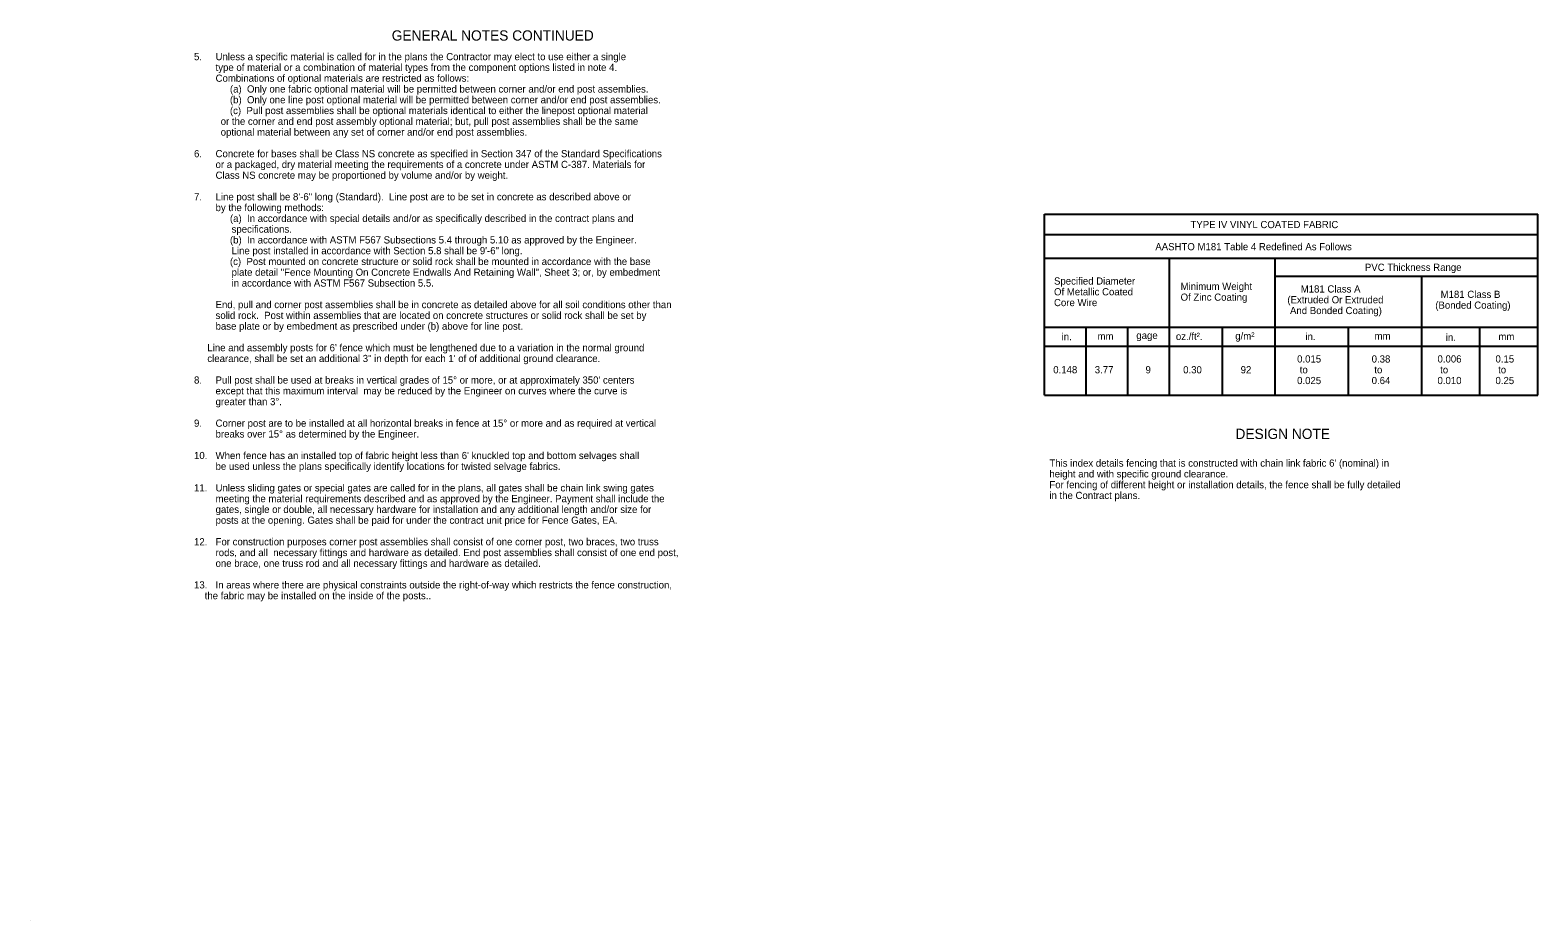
# Model space of a CAD drawing. Extents: x 10000 to 10735, y 10000 to 10434.
import ezdxf

# ---------------------------------------------------------------- set-up
doc = ezdxf.new("R2010")
doc.units = 0
for name, color, linetype in [('AdhocPoint_dp', 7, 'Continuous'), ('Default', 7, 'Continuous'), ('IndexDetail_1', 7, 'Continuous'), ('IndexDetail_2', 7, 'Continuous'), ('TextStructures', 7, 'Continuous')]:
    doc.layers.add(name, color=color, linetype=linetype)

msp = doc.modelspace()

# ---------------------------------------------------------------- linework, layer by layer
at = {"layer": 'AdhocPoint_dp'}
msp.add_line((10000, 10000), (10000, 10000), dxfattribs=at)
at = {"layer": 'Default'}
msp.add_line((10000, 10000), (10000, 10000), dxfattribs=at)
at = {"layer": 'IndexDetail_1'}
for p, q in [((10494.32, 10334.22), (10734.67, 10334.22)), ((10494.32, 10322.7), (10734.67, 10322.7)), ((10555.24, 10255.98), (10555.24, 10322.7)), ((10606.71, 10255.98), (10606.71, 10322.7)), ((10606.71, 10313.86), (10734.67, 10313.86)), ((10678.17, 10255.98), (10678.17, 10313.86)), ((10494.32, 10289.08), (10734.67, 10289.08)), ((10514.63, 10255.98), (10514.63, 10289.08)), ((10534.93, 10255.98), (10534.93, 10289.08)), ((10580.97, 10255.98), (10580.97, 10289.08)), ((10642.44, 10255.98), (10642.44, 10289.08)), ((10706.42, 10255.98), (10706.42, 10289.08)), ((10494.32, 10279.83), (10734.67, 10279.83))]:
    msp.add_line(p, q, dxfattribs=at)
at = {"layer": 'IndexDetail_2'}
for p, q in [((10494.32, 10255.98), (10494.32, 10344.12)), ((10494.32, 10344.12), (10734.67, 10344.12)), ((10734.67, 10255.98), (10734.67, 10344.12)), ((10494.32, 10255.98), (10734.67, 10255.98))]:
    msp.add_line(p, q, dxfattribs=at)

# ---------------------------------------------------------------- texts
at = {"layer": 'TextStructures'}
for s, height, p in [('GENERAL NOTES CONTINUED', 5, (10176.19, 10428.66)), ('5.', 3.5, (10079.85, 10419.11)), ('Unless a specific material is called for in the plans the Contractor may elect to use either a single', 3.5, (10090.35, 10419.11)), ('type of material or a combination of material types from the component options listed in note 4. ', 3.5, (10090.35, 10413.86)), ('Combinations of optional materials are restricted as follows:', 3.5, (10090.35, 10408.61)), ('(a)  Only one fabric optional material will be permitted between corner and/or end post assemblies.', 3.5, (10097.35, 10403.36)), ('(b)  Only one line post optional material will be permitted between corner and/or end post assemblies.', 3.5, (10097.35, 10398.11)), ('(c)  Pull post assemblies shall be optional materials identical to either the linepost optional material', 3.5, (10097.35, 10392.86)), ('          or the corner and end post assembly optional material; but, pull post assemblies shall be the same', 3.5, (10079.85, 10387.61)), ('          optional material between any set of corner and/or end post assemblies.', 3.5, (10079.85, 10382.36)), ('6.', 3.5, (10079.85, 10371.86)), ('Concrete for bases shall be Class NS concrete as specified in Section 347 of the Standard Specifications', 3.5, (10090.35, 10371.86)), ('or a packaged, dry material meeting the requirements of a concrete under ASTM C-387. Materials for', 3.5, (10090.35, 10366.61)), ('Class NS concrete may be proportioned by volume and/or by weight.', 3.5, (10090.35, 10361.36)), ('7.', 3.5, (10079.85, 10350.86)), ('Line post shall be 8\'-6" long (Standard).  Line post are to be set in concrete as described above or ', 3.5, (10090.35, 10350.86)), ('by the following methods:', 3.5, (10090.35, 10345.61)), ('(a)  In accordance with special details and/or as specifically described in the contract plans and', 3.5, (10097.35, 10340.36)), ('      specifications.', 3.5, (10090.35, 10335.11)), ('TYPE IV VINYL COATED FABRIC', 3.5, (10565.41, 10337.33)), ('(b)  In accordance with ASTM F567 Subsections 5.4 through 5.10 as approved by the Engineer.', 3.5, (10097.35, 10329.86)), ('AASHTO M181 Table 4 Redefined As Follows', 3.5, (10548.28, 10326.56)), ('(c)  Post mounted on concrete structure or solid rock shall be mounted in accordance with the base', 3.5, (10097.35, 10319.36)), ('      Line post installed in accordance with Section 5.8 shall be 9\'-6" long.', 3.5, (10090.35, 10324.61)), ('      plate detail "Fence Mounting On Concrete Endwalls And Retaining Wall", Sheet 3; or, by embedment', 3.5, (10090.35, 10314.11)), ('PVC Thickness Range', 3.5, (10650.39, 10316.52)), ('      in accordance with ASTM F567 Subsection 5.5.', 3.5, (10090.35, 10308.86)), ('Specified Diameter', 3.5, (10498.91, 10309.84)), ('Of Metallic Coated', 3.5, (10498.91, 10304.59)), ('Minimum Weight', 3.5, (10560.59, 10307.22)), ('     M181 Class A', 3.5, (10612.62, 10305.97)), ('End, pull and corner post assemblies shall be in concrete as detailed above for all soil conditions other than', 3.5, (10090.35, 10298.36)), ('Core Wire', 3.5, (10498.91, 10299.34)), ('Of Zinc Coating', 3.5, (10560.59, 10301.97)), ('(Extruded Or Extruded', 3.5, (10612.62, 10300.72)), ('(Bonded Coating)', 3.5, (10684.69, 10298.09)), ('  M181 Class B', 3.5, (10684.69, 10303.34)), ('solid rock.  Post within assemblies that are located on concrete structures or solid rock shall be set by', 3.5, (10090.35, 10293.11)), (' And Bonded Coating)', 3.5, (10612.62, 10295.47)), ('base plate or by embedment as prescribed under (b) above for line post.', 3.5, (10090.35, 10287.86)), ('in.', 3.5, (10502.61, 10282.76)), ('mm', 3.5, (10520.11, 10282.95)), ('gage', 3.5, (10539.02, 10283.34)), ('oz./ft².', 3.5, (10558.3, 10282.87)), ('g/m²', 3.5, (10587.23, 10283.08)), ('in.', 3.5, (10621.44, 10282.81)), ('mm', 3.5, (10655.09, 10283.08)), ('in.', 3.5, (10689.83, 10282.4)), ('mm', 3.5, (10715.42, 10282.81)), ("     Line and assembly posts for 6' fence which must be lengthened due to a variation in the normal ground", 3.5, (10079.85, 10277.36)), ('     clearance, shall be set an additional 3" in depth for each 1\' of of additional ground clearance.', 3.5, (10079.85, 10272.11)), ('0.015', 3.5, (10617.36, 10271.88)), ('0.38', 3.5, (10653.69, 10271.88)), ('0.006', 3.5, (10685.77, 10271.88)), ('0.15', 3.5, (10714.02, 10271.88)), ('8.', 3.5, (10079.85, 10261.61)), ("Pull post shall be used at breaks in vertical grades of 15° or more, or at approximately 350' centers", 3.5, (10090.35, 10261.61)), ('0.148', 3.5, (10498.53, 10266.63)), ('3.77', 3.5, (10518.77, 10266.63)), ('9', 3.5, (10543.5, 10266.63)), ('0.30', 3.5, (10561.84, 10266.63)), ('92', 3.5, (10589.86, 10266.63)), ('0.025', 3.5, (10617.36, 10261.38)), (' to', 3.5, (10617.36, 10266.63)), ('0.64', 3.5, (10653.69, 10261.38)), (' to', 3.5, (10653.69, 10266.63)), ('0.010', 3.5, (10685.77, 10261.38)), (' to', 3.5, (10685.77, 10266.63)), ('0.25', 3.5, (10714.02, 10261.38)), (' to', 3.5, (10714.02, 10266.63)), ('except that this maximum interval  may be reduced by the Engineer on curves where the curve is', 3.5, (10090.35, 10256.36)), ('greater than 3°.', 3.5, (10090.35, 10251.11)), ('9.', 3.5, (10079.85, 10240.61)), ('Corner post are to be installed at all horizontal breaks in fence at 15° or more and as required at vertical', 3.5, (10090.35, 10240.61)), ('breaks over 15° as determined by the Engineer.', 3.5, (10090.35, 10235.36)), ('DESIGN NOTE', 5, (10587.33, 10234.65)), ('10.', 3.5, (10079.85, 10224.86)), ("When fence has an installed top of fabric height less than 6' knuckled top and bottom selvages shall", 3.5, (10090.35, 10224.86)), ('be used unless the plans specifically identify locations for twisted selvage fabrics.', 3.5, (10090.35, 10219.61)), ("This index details fencing that is constructed with chain link fabric 6' (nominal) in ", 3.5, (10496.65, 10221.17)), ('height and with specific ground clearance.  ', 3.5, (10496.65, 10215.92)), ('11.', 3.5, (10079.85, 10209.11)), ('Unless sliding gates or special gates are called for in the plans, all gates shall be chain link swing gates', 3.5, (10090.35, 10209.11)), ('For fencing of different height or installation details, the fence shall be fully detailed ', 3.5, (10496.65, 10210.67)), ('meeting the material requirements described and as approved by the Engineer. Payment shall include the', 3.5, (10090.35, 10203.86)), ('in the Contract plans.', 3.5, (10496.65, 10205.42)), ('gates, single or double, all necessary hardware for installation and any additional length and/or size for', 3.5, (10090.35, 10198.61)), ('posts at the opening. Gates shall be paid for under the contract unit price for Fence Gates, EA.', 3.5, (10090.35, 10193.36)), ('12.', 3.5, (10079.85, 10182.86)), ('For construction purposes corner post assemblies shall consist of one corner post, two braces, two truss', 3.5, (10090.35, 10182.86)), ('one brace, one truss rod and all necessary fittings and hardware as detailed.', 3.5, (10090.35, 10172.36)), ('rods, and all  necessary fittings and hardware as detailed. End post assemblies shall consist of one end post,', 3.5, (10090.35, 10177.61)), ('13.', 3.5, (10079.85, 10161.86)), ('In areas where there are physical constraints outside the right-of-way which restricts the fence construction,', 3.5, (10090.35, 10161.86)), ('    the fabric may be installed on the inside of the posts..', 3.5, (10079.85, 10156.61))]:
    msp.add_text(s, height=height, dxfattribs=at).set_placement(p)

doc.saveas('drawing.dxf')
